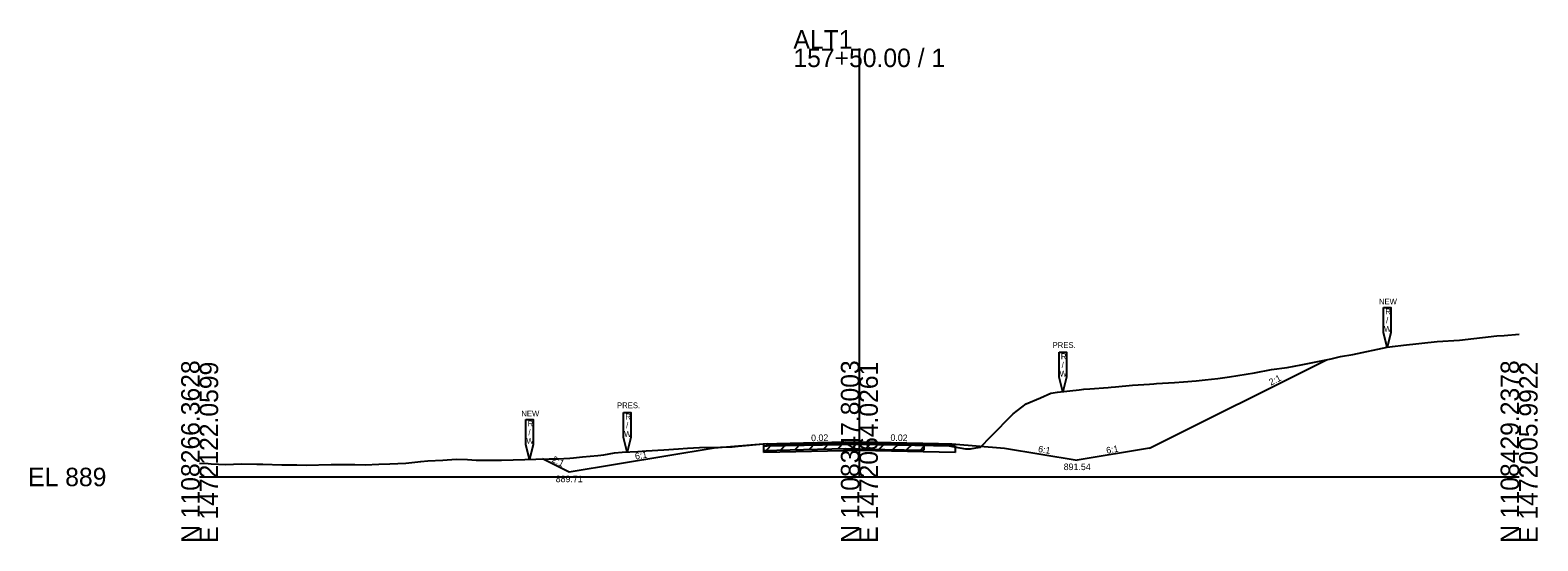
# Model space of a CAD drawing. Extents: x -26 to 2203, y -10 to 19568.
# Drawn here: x -25.7 to 202.8, y 19490.3 to 19567.8 of the extents above; entities that cross this region are included whole.
import ezdxf

# ---------------------------------------------------------------- set-up
doc = ezdxf.new("R2010")
doc.units = 0
for name, color, linetype in [('RD_GPK_XS_Cell', 7, 'Continuous'), ('RD_XS_Base', 7, 'Continuous'), ('RD_XS_ExGround', 7, 'Continuous'), ('RD_XS_ExPaveRet', 7, 'Continuous'), ('RD_XS_ExRW', 7, 'Continuous'), ('RD_XS_Greenside', 7, 'Continuous'), ('RD_XS_NewRW', 7, 'Continuous'), ('RD_XS_Pave', 7, 'Continuous'), ('RD_XS_TieSlope', 7, 'Continuous'), ('RD_XS_TX_Slope', 7, 'Continuous')]:
    doc.layers.add(name, color=color, linetype=linetype)

msp = doc.modelspace()

# ---------------------------------------------------------------- linework, layer by layer
at = {"layer": 'RD_GPK_XS_Cell'}
for p, q in [((100, 19500), (100, 19564.98)), ((0, 19500), (100, 19500)), ((100, 19500), (200, 19500))]:
    msp.add_line(p, q, dxfattribs=at)
at = {"layer": 'RD_XS_Base'}
for points in [[(85.5, 19504.71), (86, 19504.72), (100, 19505), (114, 19504.72), (114.5, 19504.71)], [(85.5, 19503.71), (85.5, 19504.71)], [(114.5, 19503.71), (100, 19504), (85.5, 19503.71)], [(114.5, 19504.71), (114.5, 19503.71)]]:
    msp.add_lwpolyline(points, dxfattribs=at)
at = {"layer": 'RD_XS_ExGround'}
msp.add_lwpolyline([(0, 19502.07), (1.3, 19502.06), (1.76, 19502.01), (3.95, 19501.87), (6.27, 19501.98), (8.69, 19501.96), (9.58, 19501.93), (12.45, 19501.86), (14.75, 19501.83), (16.13, 19501.8), (19.92, 19501.91), (23.5, 19501.87), (25.09, 19501.85), (27.16, 19501.93), (28.83, 19502.01), (31.24, 19502.07), (33.53, 19502.36), (34.59, 19502.45), (36.88, 19502.56), (38.86, 19502.69), (40.6, 19502.63), (41.92, 19502.57), (43.52, 19502.55), (45.77, 19502.55), (49.29, 19502.66), (50.94, 19502.71), (52.97, 19502.75), (54.27, 19502.76), (56.11, 19502.86), (56.65, 19502.89), (58.01, 19503.03), (60.34, 19503.25), (61.27, 19503.38), (62.88, 19503.66), (64.02, 19503.75), (66.44, 19503.87), (67.7, 19503.96), (70.38, 19504.13), (72.6, 19504.29), (73.94, 19504.38), (75.74, 19504.46), (78.97, 19504.53), (80.74, 19504.59), (81.61, 19504.69), (85.46, 19505.03), (91.52, 19505.17), (97.95, 19505.32), (100, 19505.27), (103.88, 19505.18), (109.77, 19505.06), (112, 19504.94), (112.54, 19504.94), (114.39, 19504.56), (116.09, 19504.26), (116.83, 19504.26), (117.64, 19504.4), (118.36, 19504.53), (119.93, 19506.16), (123.31, 19509.56), (125.26, 19511.09), (127.43, 19512.03), (129.03, 19512.71), (130.04, 19512.84), (133.31, 19513.24), (134.01, 19513.33), (134.92, 19513.39), (137.7, 19513.59), (138.16, 19513.63), (138.82, 19513.68), (141.38, 19513.91), (143.98, 19514.1), (144.62, 19514.14), (145.06, 19514.17), (147.74, 19514.33), (149.15, 19514.42), (151.07, 19514.6), (152.43, 19514.76), (154.32, 19514.96), (156.12, 19515.18), (159.9, 19515.81), (162.47, 19516.29), (164.82, 19516.61), (165.91, 19516.79), (166.94, 19517.01), (171.51, 19517.92), (172.95, 19518.27), (174.8, 19518.6), (180.01, 19519.67), (180.83, 19519.8), (182.5, 19519.99), (187.6, 19520.57), (190.95, 19520.75), (196.64, 19521.39), (197.74, 19521.48), (200, 19521.66)], dxfattribs=at)
at = {"layer": 'RD_XS_ExPaveRet'}
for p, q in [((94.56, 19504.24), (95.59, 19505.27)), ((96.73, 19504.29), (97.76, 19505.32)), ((98.86, 19504.3), (99.84, 19505.28)), ((85.46, 19505.03), (85.46, 19504.03)), ((85.87, 19504.04), (86.9, 19505.06)), ((88.04, 19504.09), (89.07, 19505.11)), ((90.22, 19504.14), (91.24, 19505.16)), ((92.39, 19504.19), (93.41, 19505.21)), ((100.94, 19504.25), (101.91, 19505.23)), ((103.01, 19504.2), (103.98, 19505.18)), ((105.08, 19504.16), (106.06, 19505.14)), ((107.16, 19504.11), (108.14, 19505.09)), ((109.24, 19504.07), (109.77, 19504.6)), ((109.77, 19505.06), (109.77, 19504.06))]:
    msp.add_line(p, q, dxfattribs=at)
msp.add_lwpolyline([(85.46, 19504.03), (91.55, 19504.17), (97.95, 19504.32), (103.86, 19504.18), (109.77, 19504.06)], dxfattribs=at)
at = {"layer": 'RD_XS_ExRW'}
for points in [[(130.28, 19518.95), (131.37, 19518.95), (131.37, 19515.12), (130.82, 19512.93), (130.28, 19515.12)], [(64.26, 19509.8), (65.36, 19509.8), (65.36, 19505.97), (64.81, 19503.78), (64.26, 19505.97)]]:
    msp.add_lwpolyline(points, close=True, dxfattribs=at)
at = {"layer": 'RD_XS_Greenside'}
for points in [[(78, 19504.37), (56, 19500.71)], [(86, 19505.04), (78, 19504.37)], [(114, 19505.04), (122, 19504.37)], [(122, 19504.37), (133, 19502.54)], [(144, 19504.37), (133, 19502.54)]]:
    msp.add_lwpolyline(points, dxfattribs=at)
at = {"layer": 'RD_XS_NewRW'}
for points in [[(179.45, 19525.69), (180.55, 19525.69), (180.55, 19521.86), (180, 19519.67), (179.45, 19521.86)], [(49.45, 19508.7), (50.55, 19508.7), (50.55, 19504.87), (50, 19502.68), (49.45, 19504.87)]]:
    msp.add_lwpolyline(points, close=True, dxfattribs=at)
at = {"layer": 'RD_XS_Pave'}
for points in [[(86, 19505.04), (88, 19505.08), (100, 19505.32), (112, 19505.08), (114, 19505.04)], [(86, 19504.88), (100, 19505.16), (114, 19504.88)], [(114, 19504.88), (100, 19505.16), (86, 19504.88)], [(86, 19504.88), (86, 19505.04)], [(114, 19504.72), (100, 19505), (86, 19504.72)], [(86, 19504.72), (86, 19504.88)], [(114, 19505.04), (114, 19504.88)], [(114, 19504.88), (114, 19504.72)]]:
    msp.add_lwpolyline(points, dxfattribs=at)
at = {"layer": 'RD_XS_TieSlope'}
for points in [[(144, 19504.37), (170.82, 19517.78)], [(56, 19500.71), (51.95, 19502.73)]]:
    msp.add_lwpolyline(points, dxfattribs=at)

# ---------------------------------------------------------------- texts
at = {"layer": 'RD_GPK_XS_Cell'}
for s, p in [('ALT1', (90, 19564.98)), ('157+50.00 / 1', (90, 19562.18)), ('EL 889', (-26, 19498.6))]:
    msp.add_text(s, height=2.8, dxfattribs=at).set_placement(p)
for s, p in [('N 1108266.3628', (0, 19490)), ('E 1472122.0599', (2.8, 19490)), ('N 1108347.8003', (100, 19490)), ('E 1472064.0261', (102.8, 19490)), ('N 1108429.2378', (200, 19490)), ('E 1472005.9922', (202.8, 19490))]:
    msp.add_text(s, height=2.8, rotation=90, dxfattribs=at).set_placement(p)
at = {"layer": 'RD_XS_ExRW'}
for s, p in [('PRES.', (129.28, 19519.58)), ('R', (130.54, 19517.86)), ('/', (130.66, 19516.55)), ('W', (130.35, 19515.23)), ('PRES.', (63.26, 19510.43)), ('R', (64.52, 19508.71)), ('/', (64.64, 19507.4)), ('W', (64.34, 19506.08))]:
    msp.add_text(s, height=0.875, dxfattribs=at).set_placement(p)
at = {"layer": 'RD_XS_NewRW'}
for s, p in [('NEW', (178.75, 19526.17)), ('R', (179.71, 19524.65)), ('/', (179.83, 19523.33)), ('W', (179.53, 19522.02)), ('NEW', (48.75, 19509.18)), ('R', (49.71, 19507.66)), ('W', (49.53, 19505.03)), ('/', (49.83, 19506.34))]:
    msp.add_text(s, height=0.875, dxfattribs=at).set_placement(p)
at = {"layer": 'RD_XS_TX_Slope'}
for s, rotation, p in [('2:1', 26.5651, (162.38, 19513.84)), ('0.02', 1.1458, (92.69, 19505.42)), ('0.02', 358.8542, (104.7, 19505.48)), ('2:1', 333.4349, (53.29, 19502.34)), ('6:1', 9.4642, (66.07, 19502.64)), ('6:1', 350.5358, (127.04, 19503.79)), ('6:1', 10.416, (137.51, 19503.51))]:
    msp.add_text(s, height=1, rotation=rotation, dxfattribs=at).set_placement(p)
for s, p in [('891.54', (130.97, 19501.04)), ('889.71', (53.97, 19499.21))]:
    msp.add_text(s, height=1, dxfattribs=at).set_placement(p)

doc.saveas('drawing.dxf')
